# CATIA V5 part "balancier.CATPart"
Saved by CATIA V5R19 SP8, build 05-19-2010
Part number: balancier
Bounding box of the stored display mesh (mm): x 58 to 79, y 236.595 to 277.534, z 51.208 to 120.521
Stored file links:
  G:\EU_thinkMotion\CFAO_2010\MMS_groupe3\MMS_groupe3\A reprendre\amenand\amenand\balancier.CATPart
  F:\thinkmotion CFAO v12.1\essuie_glace.CATProduct
  G:\EU_thinkMotion\CFAO_2010\MMS_groupe3\MMS_groupe3\A reprendre\amenand\amenand\squelette_biellette1.CATPart
  G:\EU_thinkMotion\CFAO_2010\MMS_groupe3\MMS_groupe3\A reprendre\amenand\amenand\squelette_biellette2.CATPart
  G:\EU_thinkMotion\CFAO_2010\MMS_groupe3\MMS_groupe3\A reprendre\amenand\amenand\bati.CATPart
  G:\EU_thinkMotion\CFAO_2010\MMS_groupe3\MMS_groupe3\A reprendre\amenand\amenand\squelette_bati.CATPart
  G:\EU_thinkMotion\CFAO_2010\MMS_groupe3\MMS_groupe3\A reprendre\amenand\amenand\squelette_de_base.CATPart
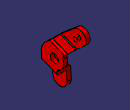
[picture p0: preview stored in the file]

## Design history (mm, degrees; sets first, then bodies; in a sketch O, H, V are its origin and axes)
Set1
  Point1 to Point3: linked copy from another document
  Line1: linked copy from another document
  Plane1: linked copy from another document
  Line2: linked copy from another document
  Plane2: linked copy from another document
  Plane3: linked copy from another document
  Point4: linked copy from another document
  Point5: linked copy from another document
  Line3: linked copy from another document
  Line4: linked copy from another document
  Point6: linked copy from another document
  Point7: linked copy from another document
Body1 (main body)
  Line5: type PtPt, FirstPoint Point1, SecondPoint Point2
  Plane4: type 2Lines, Element1 Line5, Element2 Line1
  Sketch1 on Plane1, origin (74, 0, 0), H (0, 1, 0), V (0, 0, 1)
    arc A1 centre (269.0657, 112.0523) radius 8.5 from (274.537, 105.5473) to (263.5944, 118.5573) ccw
    point P1 (269.0657, 112.0523)
    arc A2 centre (246.6094, 59.6969) radius 8.5 from (238.1207, 59.2575) to (255.098, 60.1363) ccw
    point P2 (246.6094, 59.6969)
    arc A3 centre (251.964, 88.354) radius 11 from (256.7114, 78.4312) to (262.1728, 92.4504) ccw
    point P3 (251.964, 88.354)
    reference projected point E1 (251.964, 88.354) from Point3
    line L1 (274.537, 105.5473) -> (263.0953, 95.9237)
    line L2 (255.098, 60.1363) -> (254.3291, 74.9908)
    line L3 (238.1207, 59.2575) -> (236.5946, 88.7416)
    line L4 (263.5944, 118.5573) -> (242.5871, 100.8882)
    connectcurve C1
    connectcurve C2
    connectcurve C3
    reference projected line E4 (238.144, 58.808) -> (237.173, 77.567) from Line3
    reference projected line E5 (261.863, 117.101) -> (249.019, 106.298) from Line4
    reference projected point E6 (246.6094, 59.6969) from Point6
    reference projected point E7 (269.0657, 112.0523) from Point7
    radius A1 = 8.5
    radius A2 = 8.5
    radius A3 = 11
    distance L3 L2 = 17
    distance L1 L4 = 17
    distance C1 A3 = 26.4597
    coincidence: P3 E1, L3 E4, L4 E5, P2 E6, E7 P1
  Sketch2 on Plane4, origin (0, 191.5894, -77.266), H (-1, 0, 0), V (0, 0.374, 0.9274)
    line L1 (-74, 185.6807) -> (-74, 166.6807)
    point P1 (-74, 187.6807)
    reference intersected line E1 through (-74, 0) direction (0, -1) from Plane1
    line L2 (-79, 188.6807) -> (-79, 163.6807)
    line L3 (-72, 187.6807) -> (-64, 187.6807)
    line L4 (-62, 189.6807) -> (-62, 218.6137)
    line L5 (-62, 218.6137) -> (-67, 218.6137)
    line L6 (-67, 218.6137) -> (-67, 191.6807)
    line L7 (-77, 190.6807) -> (-68, 190.6807)
    line L8 (-72, 164.6807) -> (-64, 164.6807)
    point P4 (-62, 164.6807)
    line L9 (-62, 162.6807) -> (-62, 138.6137)
    line L10 (-62, 138.6137) -> (-67, 138.6137)
    point P6 (-67, 138.6137)
    line L11 (-67, 138.6137) -> (-67, 160.6807)
    line L12 (-68, 161.6807) -> (-77, 161.6807)
    reference projected line E2 (-63, 176.1807) -> (-103, 176.1807) from Line2
    reference intersected line E3 through (-67, 0) direction (0, -1) from Plane2
    reference intersected line E4 through (-62, 0) direction (0, -1) from Plane3
    arc A1 centre (-64, 189.6807) radius 2 from (-64, 187.6807) to (-62, 189.6807) ccw
    arc A2 centre (-68, 191.6807) radius 1 from (-67, 191.6807) to (-68, 190.6807) cw
    arc A3 centre (-77, 188.6807) radius 2 from (-77, 190.6807) to (-79, 188.6807) ccw
    arc A4 centre (-72, 185.6807) radius 2 from (-72, 187.6807) to (-74, 185.6807) ccw
    arc A5 centre (-72, 166.6807) radius 2 from (-72, 164.6807) to (-74, 166.6807) cw
    arc A6 centre (-77, 163.6807) radius 2 from (-79, 163.6807) to (-77, 161.6807) ccw
    arc A7 centre (-68, 160.6807) radius 1 from (-68, 161.6807) to (-67, 160.6807) cw
    arc A8 centre (-64, 162.6807) radius 2 from (-62, 162.6807) to (-64, 164.6807) ccw
    distance L2 L1 = 5
    distance L7 L3 = 3
    distance L8 L12 = 3
    distance E2 L3 = 11.5
    radius A1 = 2
    radius A2 = 1
    radius A3 = 2
    radius A4 = 2
    distance L8 L3 = 23
    radius A5 = 2
    radius A6 = 2
    radius A7 = 1
    radius A8 = 2
    distance L5 L10 = 80
    vertical: L1 V, L2 V, L4 V, L6 V, L9 V, L11 V
    coincidence: L1 E1, P4 L4, P6 L6, L6 E3, L4 E4, L3 P1, L1 P1, L9 P4, L8 P4
    horizontal: L3 H, L5 H, L7 H, L8 H, L10 H, L12 H
    tangency: A1 L3, A1 L4, A2 L6, A2 L7, A3 L7, A3 L2, A4 L3, A4 L1, A5 L8, A5 L1, A6 L2, A6 L12, A7 L12, A7 L11, A8 L9, A8 L8
  SolidCombine1: FirstComponentProfile Sketch1, FirstComponentDirection Sketch1, SecondComponentProfile Sketch2, SecondComponentDirection Sketch2
  Sketch3 on face of SolidCombine1 from Sketch2.L2, origin (79, 252.1455, 93.7565), H (0, 1, 0), V (0, 0, 1)
    point P1 (-0.1815, -5.4025)
    reference projected point E1 (-0.1815, -5.4025) from Point4
    coincidence: P1 E1
  Hole1: placed by Sketch3, at (79, 251.964, 88.354) direction (-1, 0, 0), diameter 10, through (limit type 6)
  Sketch4 on face of SolidCombine1 from Sketch2.L6, origin (67, 270.5189, 118.4483), H (0, -0.374, -0.9274), V (0, 0.9274, -0.374)
    circle A1 centre (6.4753, 1.0445) radius 2.5
    point P1 (6.4753, 1.0445)
    reference projected point E1 (6.4753, 1.0445) from Point7
    radius A1 = 2.5
    coincidence: P1 E1
  Pad1: profile Sketch4, direction (1, 0, 0), length 4
  Sketch5 on face of SolidCombine1 from Sketch2.L9, origin (62, 262.5336, 98.6479), H (0, 0.374, 0.9274), V (0, 0.9274, -0.374)
    circle A1 centre (-42.0799, -0.2) radius 2.5
    point P1 (-42.0799, -0.2)
    reference projected point E1 (-42.0799, -0.2) from Point6
    radius A1 = 2.5
    coincidence: P1 E1
  Pad2: profile Sketch5, direction (-1, 0, 0), length 4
